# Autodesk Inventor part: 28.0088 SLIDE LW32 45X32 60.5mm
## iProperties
Created: 2007-06
Part Number: 28.0088 SLIDE LW32 45X32 60.5mm
Material: Aluminum-6061
Document SubType Name: Modeling
Designer: Andy Moles
Density: 2.71 g/cm^3
Author: Andy Moles
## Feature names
1. Extrusion1
